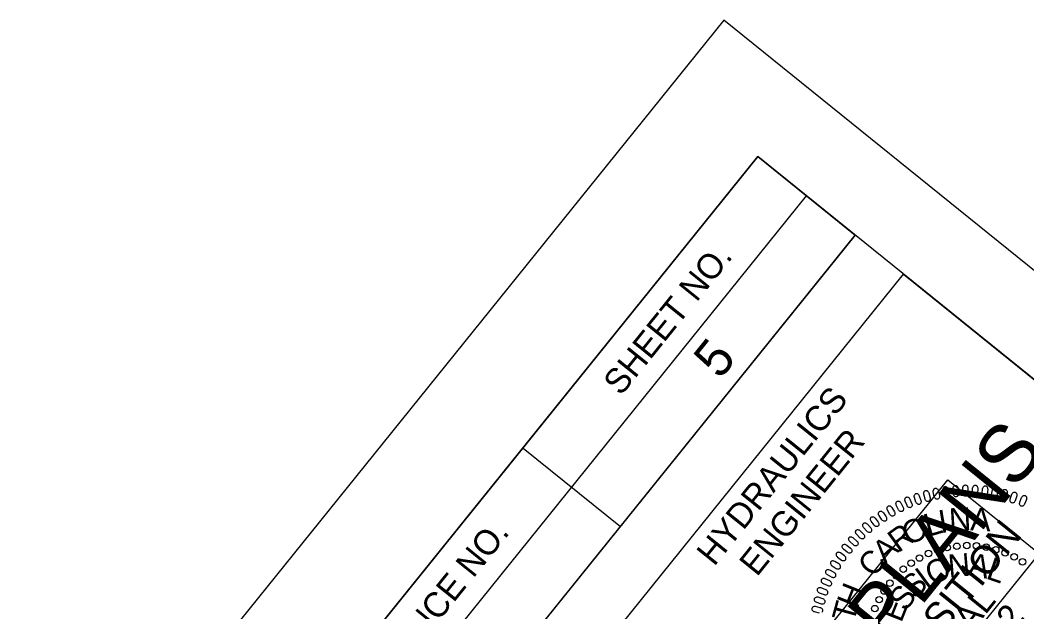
# Model space of a CAD drawing. Extents: x 1487832 to 1490056, y 498345 to 500343.
# Drawn here: x 1488790.9 to 1488992.8, y 500224.6 to 500343.2 of the extents above; entities that cross this region are included whole.
import ezdxf

# ---------------------------------------------------------------- set-up
doc = ezdxf.new("R2010")
doc.units = 0
for name, color, linetype in [('Old_Level_9', 7, 'Continuous'), ('Sheet Data Field CELL', 7, 'Continuous'), ('Sheet Plan CELL', 7, 'Continuous'), ('Sheet Plot Border Outside CELL', 7, 'Continuous'), ('Sheet Sticker Incomplete CELL', 7, 'Continuous')]:
    doc.layers.add(name, color=color, linetype=linetype)

msp = doc.modelspace()

# ---------------------------------------------------------------- linework, layer by layer
at = {"layer": 'Old_Level_9'}
for points in [[(1488972.37, 500247.2), (1488972.11, 500248.15), (1488972.09, 500248.33), (1488972.11, 500248.45), (1488972.16, 500248.61), (1488972.21, 500248.72), (1488972.28, 500248.8), (1488972.35, 500248.86), (1488972.44, 500248.9), (1488972.53, 500248.9), (1488972.63, 500248.91), (1488972.72, 500248.88), (1488972.83, 500248.83), (1488972.89, 500248.78), (1488972.97, 500248.67), (1488973.06, 500248.55), (1488973.11, 500248.42), (1488973.38, 500247.44), (1488973.4, 500247.31), (1488973.39, 500247.19), (1488973.36, 500247.04), (1488973.3, 500246.91), (1488973.24, 500246.83), (1488973.13, 500246.75), (1488973.02, 500246.7), (1488972.89, 500246.7), (1488972.8, 500246.72), (1488972.68, 500246.77), (1488972.55, 500246.88), (1488972.46, 500247), (1488972.41, 500247.1)], [(1488974.23, 500247.67), (1488974.03, 500248.64), (1488974.02, 500248.82), (1488974.04, 500248.94), (1488974.1, 500249.1), (1488974.16, 500249.2), (1488974.24, 500249.28), (1488974.31, 500249.33), (1488974.4, 500249.36), (1488974.49, 500249.37), (1488974.59, 500249.36), (1488974.68, 500249.33), (1488974.78, 500249.27), (1488974.84, 500249.21), (1488974.92, 500249.11), (1488975, 500248.97), (1488975.04, 500248.85), (1488975.25, 500247.86), (1488975.26, 500247.72), (1488975.25, 500247.6), (1488975.2, 500247.46), (1488975.14, 500247.33), (1488975.07, 500247.25), (1488974.96, 500247.18), (1488974.84, 500247.14), (1488974.72, 500247.14), (1488974.63, 500247.17), (1488974.51, 500247.23), (1488974.39, 500247.34), (1488974.3, 500247.47), (1488974.26, 500247.57)], [(1488976.08, 500248.02), (1488975.94, 500249), (1488975.95, 500249.18), (1488975.98, 500249.3), (1488976.05, 500249.45), (1488976.11, 500249.55), (1488976.19, 500249.62), (1488976.27, 500249.67), (1488976.36, 500249.7), (1488976.45, 500249.69), (1488976.55, 500249.68), (1488976.64, 500249.65), (1488976.74, 500249.58), (1488976.8, 500249.52), (1488976.87, 500249.41), (1488976.93, 500249.27), (1488976.97, 500249.15), (1488977.12, 500248.14), (1488977.12, 500248), (1488977.1, 500247.88), (1488977.04, 500247.74), (1488976.97, 500247.62), (1488976.9, 500247.55), (1488976.78, 500247.48), (1488976.66, 500247.45), (1488976.54, 500247.46), (1488976.45, 500247.49), (1488976.34, 500247.56), (1488976.22, 500247.68), (1488976.15, 500247.82), (1488976.11, 500247.92)], [(1488978.04, 500248.26), (1488977.96, 500249.25), (1488977.98, 500249.43), (1488978.01, 500249.54), (1488978.09, 500249.69), (1488978.16, 500249.78), (1488978.25, 500249.85), (1488978.33, 500249.89), (1488978.42, 500249.92), (1488978.51, 500249.91), (1488978.61, 500249.89), (1488978.7, 500249.85), (1488978.79, 500249.77), (1488978.84, 500249.71), (1488978.91, 500249.6), (1488978.97, 500249.45), (1488978.99, 500249.33), (1488979.08, 500248.31), (1488979.07, 500248.17), (1488979.04, 500248.06), (1488978.98, 500247.92), (1488978.9, 500247.8), (1488978.82, 500247.73), (1488978.7, 500247.68), (1488978.58, 500247.65), (1488978.46, 500247.67), (1488978.37, 500247.71), (1488978.26, 500247.78), (1488978.15, 500247.91), (1488978.09, 500248.05), (1488978.06, 500248.15)], [(1488979.96, 500248.39), (1488979.94, 500249.38), (1488979.97, 500249.56), (1488980.01, 500249.67), (1488980.1, 500249.81), (1488980.18, 500249.9), (1488980.27, 500249.97), (1488980.35, 500250), (1488980.45, 500250.02), (1488980.54, 500250), (1488980.63, 500249.98), (1488980.72, 500249.93), (1488980.8, 500249.85), (1488980.85, 500249.79), (1488980.91, 500249.67), (1488980.96, 500249.52), (1488980.98, 500249.39), (1488981, 500248.38), (1488980.98, 500248.24), (1488980.95, 500248.12), (1488980.88, 500247.99), (1488980.79, 500247.88), (1488980.71, 500247.81), (1488980.58, 500247.76), (1488980.46, 500247.75), (1488980.34, 500247.78), (1488980.25, 500247.82), (1488980.15, 500247.9), (1488980.05, 500248.03), (1488980, 500248.18), (1488979.97, 500248.28)], [(1488981.85, 500248.38), (1488981.9, 500249.37), (1488981.94, 500249.55), (1488981.99, 500249.66), (1488982.08, 500249.79), (1488982.17, 500249.88), (1488982.26, 500249.94), (1488982.35, 500249.97), (1488982.44, 500249.98), (1488982.53, 500249.96), (1488982.62, 500249.93), (1488982.71, 500249.88), (1488982.79, 500249.79), (1488982.83, 500249.72), (1488982.88, 500249.6), (1488982.92, 500249.45), (1488982.93, 500249.32), (1488982.89, 500248.31), (1488982.86, 500248.17), (1488982.82, 500248.06), (1488982.74, 500247.93), (1488982.64, 500247.82), (1488982.56, 500247.76), (1488982.43, 500247.72), (1488982.31, 500247.71), (1488982.19, 500247.75), (1488982.11, 500247.79), (1488982.01, 500247.88), (1488981.92, 500248.02), (1488981.87, 500248.17), (1488981.86, 500248.28)], [(1488983.79, 500248.28), (1488983.9, 500249.26), (1488983.95, 500249.44), (1488984, 500249.54), (1488984.11, 500249.67), (1488984.2, 500249.75), (1488984.3, 500249.8), (1488984.38, 500249.83), (1488984.48, 500249.83), (1488984.56, 500249.81), (1488984.66, 500249.77), (1488984.74, 500249.71), (1488984.81, 500249.62), (1488984.85, 500249.55), (1488984.89, 500249.43), (1488984.92, 500249.28), (1488984.93, 500249.15), (1488984.82, 500248.13), (1488984.79, 500248), (1488984.74, 500247.89), (1488984.65, 500247.77), (1488984.55, 500247.67), (1488984.46, 500247.61), (1488984.33, 500247.58), (1488984.21, 500247.58), (1488984.09, 500247.62), (1488984.01, 500247.67), (1488983.92, 500247.77), (1488983.84, 500247.91), (1488983.8, 500248.06), (1488983.79, 500248.17)], [(1488985.72, 500248.03), (1488985.9, 500249.01), (1488985.96, 500249.18), (1488986.02, 500249.28), (1488986.13, 500249.4), (1488986.22, 500249.47), (1488986.33, 500249.52), (1488986.41, 500249.54), (1488986.51, 500249.54), (1488986.59, 500249.51), (1488986.68, 500249.47), (1488986.76, 500249.4), (1488986.83, 500249.31), (1488986.86, 500249.24), (1488986.9, 500249.11), (1488986.92, 500248.96), (1488986.91, 500248.83), (1488986.74, 500247.82), (1488986.7, 500247.69), (1488986.64, 500247.59), (1488986.55, 500247.47), (1488986.44, 500247.38), (1488986.35, 500247.33), (1488986.22, 500247.3), (1488986.1, 500247.31), (1488985.98, 500247.36), (1488985.91, 500247.41), (1488985.82, 500247.51), (1488985.75, 500247.66), (1488985.72, 500247.82), (1488985.71, 500247.92)], [(1488987.6, 500247.67), (1488987.83, 500248.63), (1488987.9, 500248.8), (1488987.97, 500248.9), (1488988.09, 500249.01), (1488988.19, 500249.08), (1488988.29, 500249.12), (1488988.38, 500249.13), (1488988.48, 500249.13), (1488988.56, 500249.09), (1488988.65, 500249.04), (1488988.72, 500248.98), (1488988.78, 500248.88), (1488988.82, 500248.8), (1488988.84, 500248.67), (1488988.85, 500248.52), (1488988.84, 500248.39), (1488988.6, 500247.4), (1488988.55, 500247.27), (1488988.49, 500247.17), (1488988.39, 500247.06), (1488988.28, 500246.97), (1488988.18, 500246.93), (1488988.05, 500246.91), (1488987.93, 500246.92), (1488987.82, 500246.98), (1488987.74, 500247.04), (1488987.66, 500247.15), (1488987.6, 500247.3), (1488987.58, 500247.46), (1488987.59, 500247.56)], [(1488989.46, 500247.19), (1488989.75, 500248.14), (1488989.84, 500248.3), (1488989.91, 500248.39), (1488990.04, 500248.5), (1488990.14, 500248.56), (1488990.24, 500248.59), (1488990.34, 500248.6), (1488990.43, 500248.59), (1488990.51, 500248.54), (1488990.59, 500248.49), (1488990.66, 500248.42), (1488990.72, 500248.32), (1488990.74, 500248.24), (1488990.76, 500248.11), (1488990.76, 500247.96), (1488990.74, 500247.83), (1488990.45, 500246.86), (1488990.39, 500246.73), (1488990.32, 500246.63), (1488990.21, 500246.53), (1488990.09, 500246.45), (1488990, 500246.41), (1488989.86, 500246.4), (1488989.74, 500246.42), (1488989.63, 500246.49), (1488989.57, 500246.55), (1488989.49, 500246.66), (1488989.44, 500246.82), (1488989.43, 500246.98), (1488989.44, 500247.08)], [(1488967.04, 500245.06), (1488966.6, 500245.96), (1488966.55, 500246.13), (1488966.54, 500246.25), (1488966.56, 500246.41), (1488966.59, 500246.53), (1488966.65, 500246.62), (1488966.71, 500246.69), (1488966.79, 500246.75), (1488966.87, 500246.77), (1488966.97, 500246.79), (1488967.07, 500246.78), (1488967.18, 500246.75), (1488967.25, 500246.71), (1488967.35, 500246.63), (1488967.46, 500246.52), (1488967.53, 500246.41), (1488967.98, 500245.5), (1488968.03, 500245.36), (1488968.05, 500245.25), (1488968.04, 500245.1), (1488968, 500244.96), (1488967.96, 500244.86), (1488967.87, 500244.77), (1488967.77, 500244.7), (1488967.64, 500244.67), (1488967.55, 500244.67), (1488967.42, 500244.7), (1488967.27, 500244.78), (1488967.16, 500244.89), (1488967.09, 500244.97)], [(1488968.76, 500245.89), (1488968.38, 500246.8), (1488968.34, 500246.98), (1488968.34, 500247.1), (1488968.37, 500247.26), (1488968.41, 500247.38), (1488968.47, 500247.47), (1488968.53, 500247.53), (1488968.61, 500247.58), (1488968.7, 500247.6), (1488968.8, 500247.61), (1488968.9, 500247.6), (1488969.01, 500247.56), (1488969.08, 500247.52), (1488969.17, 500247.43), (1488969.27, 500247.31), (1488969.34, 500247.2), (1488969.73, 500246.26), (1488969.77, 500246.12), (1488969.77, 500246.01), (1488969.76, 500245.86), (1488969.72, 500245.72), (1488969.67, 500245.63), (1488969.57, 500245.54), (1488969.46, 500245.48), (1488969.34, 500245.46), (1488969.24, 500245.47), (1488969.12, 500245.5), (1488968.98, 500245.59), (1488968.87, 500245.71), (1488968.81, 500245.79)], [(1488970.55, 500246.58), (1488970.23, 500247.52), (1488970.2, 500247.7), (1488970.21, 500247.82), (1488970.25, 500247.98), (1488970.3, 500248.09), (1488970.36, 500248.18), (1488970.43, 500248.24), (1488970.51, 500248.28), (1488970.6, 500248.3), (1488970.7, 500248.3), (1488970.8, 500248.29), (1488970.9, 500248.24), (1488970.97, 500248.19), (1488971.06, 500248.09), (1488971.15, 500247.97), (1488971.21, 500247.85), (1488971.54, 500246.89), (1488971.57, 500246.76), (1488971.57, 500246.64), (1488971.55, 500246.49), (1488971.5, 500246.36), (1488971.44, 500246.27), (1488971.34, 500246.18), (1488971.23, 500246.13), (1488971.1, 500246.12), (1488971.01, 500246.13), (1488970.89, 500246.17), (1488970.75, 500246.27), (1488970.65, 500246.39), (1488970.6, 500246.49)], [(1488991.36, 500246.56), (1488991.72, 500247.49), (1488991.81, 500247.65), (1488991.89, 500247.74), (1488992.02, 500247.83), (1488992.13, 500247.89), (1488992.24, 500247.92), (1488992.33, 500247.92), (1488992.42, 500247.9), (1488992.5, 500247.85), (1488992.58, 500247.79), (1488992.64, 500247.72), (1488992.69, 500247.61), (1488992.71, 500247.54), (1488992.72, 500247.4), (1488992.71, 500247.25), (1488992.68, 500247.12), (1488992.33, 500246.17), (1488992.26, 500246.05), (1488992.19, 500245.96), (1488992.07, 500245.86), (1488991.95, 500245.79), (1488991.85, 500245.75), (1488991.71, 500245.75), (1488991.6, 500245.78), (1488991.49, 500245.86), (1488991.43, 500245.92), (1488991.36, 500246.04), (1488991.32, 500246.2), (1488991.32, 500246.35), (1488991.34, 500246.46)], [(1488963.68, 500243.06), (1488963.14, 500243.89), (1488963.07, 500244.06), (1488963.04, 500244.17), (1488963.05, 500244.34), (1488963.06, 500244.45), (1488963.1, 500244.56), (1488963.16, 500244.63), (1488963.22, 500244.7), (1488963.31, 500244.73), (1488963.4, 500244.76), (1488963.5, 500244.77), (1488963.62, 500244.75), (1488963.69, 500244.72), (1488963.8, 500244.65), (1488963.92, 500244.55), (1488964.01, 500244.46), (1488964.57, 500243.61), (1488964.63, 500243.48), (1488964.66, 500243.37), (1488964.67, 500243.22), (1488964.66, 500243.07), (1488964.63, 500242.98), (1488964.55, 500242.87), (1488964.45, 500242.79), (1488964.33, 500242.75), (1488964.24, 500242.74), (1488964.11, 500242.75), (1488963.96, 500242.81), (1488963.83, 500242.9), (1488963.75, 500242.98)], [(1488965.31, 500244.12), (1488964.82, 500244.99), (1488964.76, 500245.16), (1488964.74, 500245.28), (1488964.75, 500245.44), (1488964.78, 500245.56), (1488964.82, 500245.66), (1488964.88, 500245.73), (1488964.95, 500245.79), (1488965.04, 500245.82), (1488965.13, 500245.84), (1488965.23, 500245.84), (1488965.35, 500245.82), (1488965.42, 500245.78), (1488965.53, 500245.7), (1488965.64, 500245.6), (1488965.72, 500245.5), (1488966.23, 500244.62), (1488966.28, 500244.49), (1488966.3, 500244.37), (1488966.3, 500244.22), (1488966.28, 500244.08), (1488966.24, 500243.98), (1488966.16, 500243.88), (1488966.06, 500243.81), (1488965.94, 500243.77), (1488965.84, 500243.77), (1488965.71, 500243.79), (1488965.56, 500243.86), (1488965.44, 500243.96), (1488965.37, 500244.04)], [(1488962.15, 500241.95), (1488961.55, 500242.75), (1488961.47, 500242.91), (1488961.44, 500243.03), (1488961.43, 500243.19), (1488961.44, 500243.31), (1488961.47, 500243.42), (1488961.52, 500243.49), (1488961.59, 500243.56), (1488961.67, 500243.6), (1488961.76, 500243.64), (1488961.86, 500243.65), (1488961.97, 500243.64), (1488962.05, 500243.61), (1488962.17, 500243.55), (1488962.29, 500243.46), (1488962.39, 500243.37), (1488963, 500242.56), (1488963.07, 500242.44), (1488963.1, 500242.32), (1488963.12, 500242.18), (1488963.12, 500242.03), (1488963.09, 500241.93), (1488963.02, 500241.82), (1488962.93, 500241.73), (1488962.82, 500241.69), (1488962.72, 500241.67), (1488962.59, 500241.67), (1488962.43, 500241.72), (1488962.3, 500241.81), (1488962.22, 500241.88)], [(1488959.31, 500239.41), (1488958.62, 500240.13), (1488958.52, 500240.28), (1488958.47, 500240.39), (1488958.44, 500240.55), (1488958.44, 500240.67), (1488958.46, 500240.78), (1488958.49, 500240.86), (1488958.55, 500240.93), (1488958.63, 500240.99), (1488958.71, 500241.03), (1488958.81, 500241.06), (1488958.92, 500241.06), (1488959, 500241.05), (1488959.13, 500241), (1488959.26, 500240.93), (1488959.37, 500240.85), (1488960.08, 500240.12), (1488960.16, 500240), (1488960.21, 500239.9), (1488960.25, 500239.75), (1488960.26, 500239.61), (1488960.25, 500239.51), (1488960.19, 500239.39), (1488960.11, 500239.29), (1488960.01, 500239.23), (1488959.92, 500239.2), (1488959.79, 500239.19), (1488959.62, 500239.22), (1488959.48, 500239.29), (1488959.39, 500239.34)], [(1488960.68, 500240.74), (1488960.04, 500241.5), (1488959.94, 500241.65), (1488959.9, 500241.77), (1488959.88, 500241.93), (1488959.89, 500242.05), (1488959.91, 500242.16), (1488959.96, 500242.24), (1488960.02, 500242.31), (1488960.1, 500242.35), (1488960.19, 500242.4), (1488960.28, 500242.42), (1488960.4, 500242.41), (1488960.48, 500242.39), (1488960.6, 500242.33), (1488960.73, 500242.26), (1488960.83, 500242.17), (1488961.49, 500241.4), (1488961.56, 500241.28), (1488961.61, 500241.17), (1488961.64, 500241.02), (1488961.64, 500240.88), (1488961.62, 500240.78), (1488961.56, 500240.66), (1488961.48, 500240.57), (1488961.36, 500240.52), (1488961.27, 500240.49), (1488961.14, 500240.49), (1488960.98, 500240.53), (1488960.84, 500240.6), (1488960.76, 500240.67)], [(1488958, 500238.01), (1488957.26, 500238.68), (1488957.15, 500238.82), (1488957.1, 500238.93), (1488957.06, 500239.09), (1488957.05, 500239.21), (1488957.06, 500239.32), (1488957.09, 500239.4), (1488957.14, 500239.48), (1488957.22, 500239.54), (1488957.3, 500239.59), (1488957.39, 500239.62), (1488957.51, 500239.63), (1488957.59, 500239.62), (1488957.72, 500239.58), (1488957.86, 500239.52), (1488957.96, 500239.45), (1488958.72, 500238.76), (1488958.81, 500238.66), (1488958.87, 500238.55), (1488958.91, 500238.41), (1488958.93, 500238.27), (1488958.93, 500238.17), (1488958.88, 500238.04), (1488958.81, 500237.94), (1488958.7, 500237.87), (1488958.62, 500237.84), (1488958.49, 500237.82), (1488958.32, 500237.84), (1488958.18, 500237.9), (1488958.08, 500237.95)], [(1488956.22, 500235.83), (1488955.41, 500236.4), (1488955.25, 500236.48), (1488955.13, 500236.51), (1488954.97, 500236.52), (1488954.85, 500236.5), (1488954.74, 500236.47), (1488954.67, 500236.42), (1488954.6, 500236.35), (1488954.56, 500236.27), (1488954.53, 500236.17), (1488954.52, 500236.08), (1488954.53, 500235.96), (1488954.56, 500235.88), (1488954.63, 500235.77), (1488954.72, 500235.65), (1488954.81, 500235.56), (1488955.64, 500234.96), (1488955.76, 500234.9), (1488955.87, 500234.86), (1488956.02, 500234.85), (1488956.17, 500234.86), (1488956.27, 500234.88), (1488956.38, 500234.96), (1488956.46, 500235.05), (1488956.51, 500235.17), (1488956.52, 500235.26), (1488956.51, 500235.39), (1488956.46, 500235.55), (1488956.37, 500235.68), (1488956.3, 500235.76)], [(1488956.78, 500236.54), (1488956.01, 500237.16), (1488955.89, 500237.29), (1488955.83, 500237.4), (1488955.78, 500237.56), (1488955.76, 500237.67), (1488955.76, 500237.78), (1488955.79, 500237.87), (1488955.84, 500237.95), (1488955.91, 500238.01), (1488955.99, 500238.07), (1488956.08, 500238.11), (1488956.19, 500238.12), (1488956.27, 500238.12), (1488956.4, 500238.09), (1488956.55, 500238.03), (1488956.66, 500237.97), (1488957.45, 500237.33), (1488957.55, 500237.23), (1488957.62, 500237.13), (1488957.67, 500236.99), (1488957.7, 500236.85), (1488957.7, 500236.75), (1488957.66, 500236.62), (1488957.6, 500236.52), (1488957.5, 500236.44), (1488957.41, 500236.4), (1488957.28, 500236.37), (1488957.12, 500236.38), (1488956.97, 500236.43), (1488956.87, 500236.48)], [(1488955.11, 500234.19), (1488954.26, 500234.71), (1488954.1, 500234.78), (1488953.98, 500234.8), (1488953.81, 500234.79), (1488953.7, 500234.77), (1488953.59, 500234.73), (1488953.52, 500234.68), (1488953.46, 500234.61), (1488953.43, 500234.52), (1488953.4, 500234.43), (1488953.39, 500234.33), (1488953.42, 500234.21), (1488953.45, 500234.14), (1488953.52, 500234.03), (1488953.62, 500233.91), (1488953.72, 500233.83), (1488954.58, 500233.29), (1488954.71, 500233.23), (1488954.82, 500233.2), (1488954.97, 500233.2), (1488955.12, 500233.21), (1488955.21, 500233.25), (1488955.32, 500233.33), (1488955.4, 500233.43), (1488955.43, 500233.55), (1488955.44, 500233.64), (1488955.43, 500233.77), (1488955.36, 500233.92), (1488955.27, 500234.05), (1488955.19, 500234.12)], [(1488954.13, 500232.5), (1488953.25, 500232.97), (1488953.08, 500233.02), (1488952.96, 500233.04), (1488952.8, 500233.02), (1488952.68, 500233), (1488952.58, 500232.95), (1488952.52, 500232.89), (1488952.46, 500232.81), (1488952.43, 500232.73), (1488952.41, 500232.63), (1488952.41, 500232.53), (1488952.44, 500232.42), (1488952.47, 500232.35), (1488952.56, 500232.24), (1488952.66, 500232.13), (1488952.77, 500232.05), (1488953.66, 500231.57), (1488953.79, 500231.52), (1488953.91, 500231.5), (1488954.06, 500231.5), (1488954.2, 500231.53), (1488954.29, 500231.57), (1488954.4, 500231.66), (1488954.47, 500231.76), (1488954.5, 500231.88), (1488954.5, 500231.97), (1488954.48, 500232.1), (1488954.4, 500232.25), (1488954.3, 500232.37), (1488954.22, 500232.44)], [(1488953.26, 500230.8), (1488952.35, 500231.22), (1488952.18, 500231.26), (1488952.06, 500231.27), (1488951.9, 500231.24), (1488951.78, 500231.21), (1488951.69, 500231.15), (1488951.62, 500231.09), (1488951.57, 500231.01), (1488951.55, 500230.93), (1488951.53, 500230.83), (1488951.54, 500230.73), (1488951.57, 500230.62), (1488951.61, 500230.55), (1488951.7, 500230.45), (1488951.81, 500230.34), (1488951.92, 500230.27), (1488952.85, 500229.85), (1488952.98, 500229.81), (1488953.1, 500229.79), (1488953.25, 500229.81), (1488953.39, 500229.84), (1488953.48, 500229.89), (1488953.57, 500229.98), (1488953.64, 500230.08), (1488953.66, 500230.21), (1488953.66, 500230.3), (1488953.63, 500230.43), (1488953.54, 500230.57), (1488953.43, 500230.68), (1488953.35, 500230.75)], [(1488952.46, 500229.02), (1488951.53, 500229.37), (1488951.36, 500229.41), (1488951.24, 500229.41), (1488951.08, 500229.37), (1488950.96, 500229.33), (1488950.87, 500229.27), (1488950.81, 500229.2), (1488950.76, 500229.12), (1488950.75, 500229.03), (1488950.74, 500228.93), (1488950.75, 500228.84), (1488950.79, 500228.73), (1488950.84, 500228.66), (1488950.93, 500228.56), (1488951.05, 500228.47), (1488951.17, 500228.4), (1488952.11, 500228.04), (1488952.25, 500228), (1488952.37, 500228), (1488952.51, 500228.02), (1488952.65, 500228.06), (1488952.74, 500228.11), (1488952.83, 500228.22), (1488952.89, 500228.32), (1488952.9, 500228.45), (1488952.89, 500228.54), (1488952.86, 500228.67), (1488952.76, 500228.81), (1488952.65, 500228.91), (1488952.56, 500228.97)], [(1488951.86, 500227.21), (1488950.91, 500227.51), (1488950.73, 500227.53), (1488950.61, 500227.53), (1488950.45, 500227.48), (1488950.34, 500227.43), (1488950.26, 500227.36), (1488950.2, 500227.29), (1488950.16, 500227.21), (1488950.15, 500227.12), (1488950.14, 500227.02), (1488950.16, 500226.92), (1488950.21, 500226.82), (1488950.26, 500226.75), (1488950.36, 500226.67), (1488950.48, 500226.58), (1488950.6, 500226.52), (1488951.57, 500226.21), (1488951.71, 500226.19), (1488951.83, 500226.19), (1488951.97, 500226.22), (1488952.11, 500226.27), (1488952.19, 500226.33), (1488952.28, 500226.44), (1488952.33, 500226.55), (1488952.33, 500226.67), (1488952.32, 500226.77), (1488952.27, 500226.89), (1488952.17, 500227.02), (1488952.05, 500227.12), (1488951.96, 500227.17)]]:
    msp.add_lwpolyline(points, close=True, dxfattribs=at)
msp.add_lwpolyline([(1488951.76, 500224.54), (1488951.84, 500224.66), (1488951.88, 500224.77), (1488951.88, 500224.89), (1488951.86, 500224.99), (1488951.81, 500225.11), (1488951.69, 500225.23), (1488951.57, 500225.32), (1488951.47, 500225.37), (1488951.37, 500225.4), (1488950.41, 500225.64), (1488950.23, 500225.65), (1488950.11, 500225.64), (1488949.95, 500225.58), (1488949.85, 500225.53), (1488949.76, 500225.45), (1488949.71, 500225.38), (1488949.67, 500225.29), (1488949.67, 500225.2), (1488949.67, 500225.1), (1488949.69, 500225.01), (1488949.75, 500224.91), (1488949.8, 500224.85), (1488949.91, 500224.76), (1488950.04, 500224.68), (1488950.16, 500224.63), (1488951.15, 500224.39)], dxfattribs=at)
for centre in [(1488980.73, 500237.88), (1488973.06, 500236.28), (1488974.87, 500236.97), (1488976.83, 500237.46), (1488978.75, 500237.73), (1488982.67, 500237.81), (1488984.62, 500237.56), (1488986.54, 500237.03), (1488988.44, 500236.4), (1488969.6, 500234.35), (1488971.25, 500235.37), (1488990.24, 500235.61), (1488991.91, 500234.6), (1488966.62, 500231.78), (1488968.01, 500233.14), (1488965.33, 500230.33), (1488964.14, 500228.76), (1488963.16, 500227.03), (1488962.29, 500225.24)]:
    msp.add_circle(centre, 0.649, dxfattribs=at)
at = {"layer": 'Sheet Plan CELL'}
for p, q in [((1488823.01, 500152.21), (1488948.61, 500307.93)), ((1488832.78, 500144.35), (1488958.34, 500300.08)), ((1488832.78, 500144.35), (1488958.34, 500300.08)), ((1488891.79, 500257.37), (1488911.28, 500241.71))]:
    msp.add_line(p, q, dxfattribs=at)
for points in [[(1488938.86, 500315.83), (1487997.21, 499148.18), (1488814.55, 498489.05), (1489756.18, 499656.68)], [(1488813.25, 500160.1), (1488938.86, 500315.83), (1488958.34, 500300.08), (1488832.78, 500144.35)], [(1488905.31, 500214.39), (1488968.07, 500292.23), (1489055.66, 500221.61), (1488992.89, 500143.76)]]:
    msp.add_lwpolyline(points, close=True, dxfattribs=at)
at = {"layer": 'Sheet Plot Border Outside CELL'}
msp.add_lwpolyline([(1488727.56, 498345.32), (1489784.38, 499655.78), (1488932.01, 500343.17), (1487875.19, 499032.7)], close=True, dxfattribs=at)
at = {"layer": 'Sheet Sticker Incomplete CELL'}
msp.add_lwpolyline([(1488902.95, 500121.87), (1488884.66, 500136.62), (1488976.94, 500251.05), (1488995.23, 500236.3)], close=True, dxfattribs=at)

# ---------------------------------------------------------------- texts
at = {"layer": 'Old_Level_9'}
for s, height, rotation, p in [('I', 4.59, 9.7858, (1488975.49, 500240.33)), ('N', 4.59, 3.2965, (1488977.3, 500240.74)), ('A', 4.59, 356.8071, (1488981.37, 500240.92)), ('O', 4.59, 22.7645, (1488968.95, 500237.87)), ('L', 4.59, 16.2752, (1488972.95, 500239.57)), ('R', 4.59, 35.7433, (1488967.04, 500236.34)), ('A', 4.59, 42.2326, (1488964.4, 500234.09)), ('C', 4.59, 48.722, (1488961.94, 500231.31)), ('O', 4.59, 20.6641, (1488973.51, 500229.92)), ('N', 4.59, 4.7845, (1488977.15, 500231.47)), ('A', 4.59, 348.9049, (1488980.79, 500232.01)), ('L', 4.59, 340.9651, (1488984.39, 500231.32)), ('S', 4.59, 44.4835, (1488970.3, 500226.98)), ('I', 4.59, 36.5437, (1488972.63, 500229.06)), ('H', 4.59, 68.19, (1488958.81, 500224.99)), ('S', 4.59, 52.4233, (1488968.41, 500224.5)), ('T', 4.59, 74.6794, (1488958.08, 500222.27)), ('E', 4.59, 68.3029, (1488967.6, 500222.27)), ('SEAL', 5.051, 51.1156, (1488975.95, 500213.34)), ('053892', 5.051, 51.1156, (1488978.4, 500205.95))]:
    msp.add_text(s, height=height, rotation=rotation, dxfattribs=at).set_placement(p)
at = {"layer": 'Sheet Data Field CELL'}
msp.add_text('5', height=7.5, rotation=51.1157, dxfattribs=at).set_placement((1488931.27, 500270.98))
at = {"layer": 'Sheet Plan CELL'}
for s, height, p in [('SHEET NO.', 5, (1488911.38, 500267.71)), ('HYDRAULICS', 5, (1488930.09, 500233.54)), ('ENGINEER', 5, (1488938.65, 500231.47)), ('PROJECT REFERENCE NO.', 5.0001, (1488833.98, 500171.91))]:
    msp.add_text(s, height=height, rotation=51.1157, dxfattribs=at).set_placement(p)
at = {"layer": 'Sheet Sticker Incomplete CELL'}
for s, height, p in [('INCOMPLETE PLANS', 11.52, (1488899.47, 500136.18)), ('DO NOT USE FOR R/W ACQUISITION', 5.76, (1488906.92, 500134.35))]:
    msp.add_text(s, height=height, rotation=51.1156, dxfattribs=at).set_placement(p)

doc.saveas('drawing.dxf')
